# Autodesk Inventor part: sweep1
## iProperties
Author: Administrator
Created: 2001-01
Part Number: sweep1
Document SubType Name: Modeling
Designer: Administrator
Control State: 0
Master: False
Checked Out: False
PropertySet Name: Design Tracking Control
Shininess: 0.0
PropertySet Name: _Private Model Information
Density: 0.0
Volumn: 0.0
Area: 0.0
PropertySet Name: Model Information
